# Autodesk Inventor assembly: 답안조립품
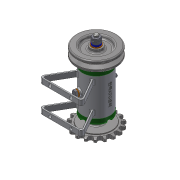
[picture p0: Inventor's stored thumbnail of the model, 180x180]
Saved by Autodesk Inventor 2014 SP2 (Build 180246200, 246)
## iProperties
Created: 2016-03
Part Number: 답안조립품
Document SubType Name: Assembly
Designer: 손기택
Author: 손기택
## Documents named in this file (16)
- C:\Users\201-15\Desktop\460307V1018\답안조립품.iam
- C:\Users\201-15\Desktop\460307V1018\본체.ipt
- C:\Users\201-15\Desktop\460307V1018\커버.ipt
- C:\Users\201-15\Desktop\460307V1018\오일 실 15 25 7.ipt
- C:\Users\201-15\Desktop\460307V1018\베어링 15 x 32 x 9.ipt
- C:\Users\201-15\Desktop\460307V1018\볼트 M4 x 12.ipt
- C:\Users\201-15\Desktop\460307V1018\축.ipt
- C:\Users\201-15\Desktop\460307V1018\키 3 x 3 x 12.ipt
- C:\Users\201-15\Desktop\460307V1018\스프로킷.ipt
- C:\Users\201-15\Desktop\460307V1018\스프링와셔 8.ipt
- C:\Users\201-15\Desktop\460307V1018\와셔 8x17.ipt
- C:\Users\201-15\Desktop\460307V1018\너트 M 8.ipt
- C:\Users\201-15\Desktop\460307V1018\V벨트풀리.ipt
- C:\Users\201-15\Desktop\460307V1018\니플 M 6 x 0.75.ipt
- C:\Users\201-15\Desktop\460307V1018\와셔 6x11.5.ipt
- C:\Users\201-15\Desktop\460307V1018\볼트 M 6 x 8.ipt
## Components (11 placed, 3 different names)
1. KS B 2023 6002 - 15 x 32 x 9:1
2. KS B 2023 6002 - 15 x 32 x 9:2
3. V벨트풀리:1
4. ISO 4762 M4 x 12:1
5. ISO 4762 M4 x 12:2
6. ISO 4762 M4 x 12:3
7. ISO 4762 M4 x 12:4
8. ISO 4762 M4 x 12:5
9. ISO 4762 M4 x 12:6
10. ISO 4762 M4 x 12:7
11. ISO 4762 M4 x 12:8
